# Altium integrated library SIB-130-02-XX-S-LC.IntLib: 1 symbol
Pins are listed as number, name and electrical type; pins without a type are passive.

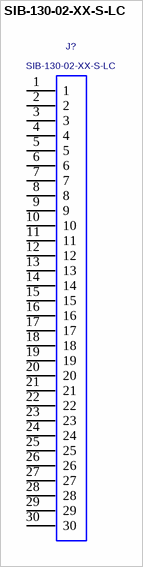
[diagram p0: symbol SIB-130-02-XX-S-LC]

## SIB-130-02-XX-S-LC
designator J?
0.100"  SINGLE INTERFACE BEAM ASSEMBLY.; MANUFACTURER: SAMTEC
footprint SIB-130-02-XX-S-LC
pins: 1, 2, 3, 4, 5, 6, 7, 8, 9, 10, 11, 12, 13, 14, 15, 16, 17, 18, 19, 20, 21, 22, 23, 24, 25, 26, 27, 28, 29, 30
